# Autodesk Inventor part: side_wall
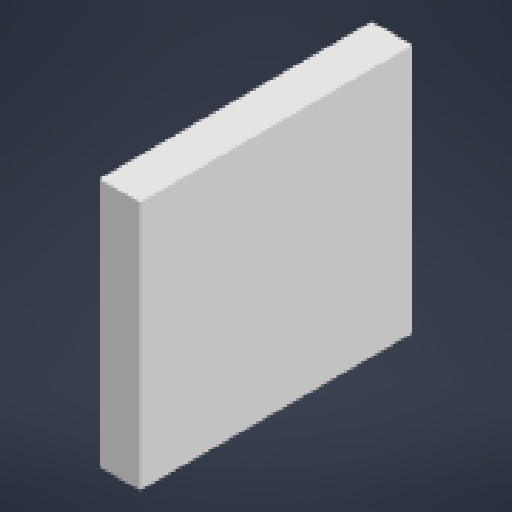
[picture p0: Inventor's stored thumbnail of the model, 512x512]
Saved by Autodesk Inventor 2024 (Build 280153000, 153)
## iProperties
Created: 2023-09
Part Number: side_wall
Material: Generic
Document SubType Name: Modeling
Designer: mammothbane
Density: 1 g/cm^3
Appearance: Default
Author: mammothbane
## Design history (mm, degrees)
sketch "Sketch1"
  geometry: L1 (75, 500)-(-75, 500); L2 (-75, 500)-(-75, -500); L3 (-75, -500)-(75, -500); L4 (75, -500)-(75, 500); L5 (75, 500)-(-75, -500); L6 (-75, 500)-(75, -500); 2 further points
  constraints: 12 end point, 2 parallel, 1 coincident, 1 horizontal, 1 midpoint, 1 perpendicular
  dimensions: "width" = 150 distance of L3.end L2.end; "length" = 1000 distance of L2.end L1.end
extrude "Extrusion1" new body sketch "Sketch1" taper "draft" = 0 deg; distance "height" = 812.8
body "Solid1"
